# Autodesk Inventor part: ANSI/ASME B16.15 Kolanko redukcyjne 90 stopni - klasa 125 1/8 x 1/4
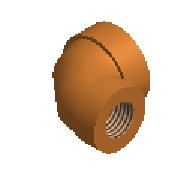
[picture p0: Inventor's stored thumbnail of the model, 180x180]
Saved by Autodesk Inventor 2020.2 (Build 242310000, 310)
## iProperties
Manager: www.cadconsulting.pl
Company: Fabian Stasiak CAD Consulting
Created: 2014-02
Part Number: ANSI/ASME B16.15 Kolanko redukcyjne 90 stopni - klasa 125 1/8 x 1/4
Material: Brąz, odlew
Description: Kolanko redukcyjne 90º odlewane z brązu, gwintowane - klasa 125
Document SubType Name: Modeling
Standard: ANSI/ASME B16.15
Designer: F.Stasiak
Standard Revision: 1985
Standards Organization: ANSI
Language: pl-PL
Size Designation: 1/8 x 1/4
Categories: <MemberInstance><Categories><Category DisplayName="Rury cienko- i grubościenne" InternalName="4347fa0f-2144-441d-94cd-e3e15c92b736" Mnemonic="TUBEANDPIPE"><Cate
Density: 1 g/cm^3
Appearance: Brąz - satynowy
Catalog Web Link: www.expertbooks.pl
NAME: PIPING: ANSI/ASME B16.15 90 Deg Elbow Reducing - Class 125
DATA: <meta><inlinegroups number="0" deflen="0"></inlinegroups><connections number="2"></connections><angles><a>1.5707963267949</a></angles></meta>
IsCustomPart: 0
Author: F.Stasiak
Subject: Zbiór ćwiczeń. Autodesk Inventor 2020. Kurs Professional
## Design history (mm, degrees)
sketch "Sketch1"
  geometry: L1 (0, 0)-(0, 8.128); L2 (0, 8.128)-(0, 9.754); L3 (0, 9.754)-(0, 16.51); L4 (0, 16.51)-(-6.756, 16.51); L5 (-6.756, 16.51)-(-8.89, 16.51); L6 (-8.89, 16.51)-(-15.24, 16.51); L7 (0, 8.128)-(-5.425, 8.128); L8 (-10.287, 0)-(-10.287, 8.128); L9 (-10.287, 8.128)-(-5.425, 8.128); L10 (-10.287, 0)-(-5.679, 0); L11 (-5.679, 0)-(-5.425, 8.128); L12 (-5.679, 0)-(0, 0); L13 (-8.89, 16.51)-(-8.89, 20.68); L14 (-8.89, 20.68)-(-15.24, 20.878); L15 (-15.24, 20.878)-(-15.24, 16.51); L16 (-8.89, 20.68)-(-8.89, 25.019); L17 (-8.89, 25.019)-(-15.24, 25.019); L18 (-15.24, 25.019)-(-15.24, 20.878); A1 r 6.756 centre (-6.756, 9.754) between (0, 9.754) and (-6.756, 16.51)
  constraints: 36 end point, 6 parallel, 5 collinear, 3 perpendicular, 2 point on circle, 2 tangent, 1 centre point, 1 horizontal, 1 vertical, 1 other
  dimensions: "d0" = 8.128 distance of L1.start L1.end (derived); "d1" = 1.6256 distance of L1.end L2.end (derived); "d2" = 16.51 distance of L1.start L3.end (derived); "d3" = 6.35 distance of L5.end L6.end (derived); "d4" = 15.24 distance of L6.end L3.end (derived); "d27" = 20.574 diameter of L8.start L1 (derived); "d28" = 11.35863 diameter of L10.end L1 (derived); "d29" = 1.78991 deg angle of L1 L11; "d30" = 1.78991 deg angle of L6 L14; "d31" = 8.73684 diameter of L14.end L6 (derived); "d32" = 17.018 diameter of L17 L6 (derived)
workplane "Work Plane1"
sketch "Sketch2" dims "d6" = 18.796 (derived)
  geometry: L1 (0, 0)-(9.398, 0); 1 further point
  constraints: 2 end point, 1 coincident, 1 horizontal, 1 horizontal alignment, 2 other
workplane "Work Plane2"
sketch "Sketch3"
  geometry: C1 r 7.62 at (0, 16.51); 1 further point
  constraints: 1 centre point, 1 coincident
  dimensions: "d8" = 15.24 diameter of C1 (derived)
sketch "Sketch4"
  geometry: L1 (-8.89, 24.13)-(-8.89, 8.89) reference; L2 (0, 8.128)-(-9.398, 8.128) reference; L3 (-9.398, 8.128)-(-8.89, 8.89); L4 (-9.144, 8.509)-(0, 16.51); 1 further point
  constraints: 4 end point, 1 midpoint, 1 point on line
  dimensions: "d9" = 8.509 distance of point (-2.74, 14.112) L4.start (derived)
workplane "Work Plane3"
sketch "Sketch5"
  geometry: L1 (-9.144, 8.509)-(0, 16.51) reference
workplane "Work Plane4"
sketch "Sketch6"
  geometry: C1 r 8.509 at (8.509, 0); 1 further point
  constraints: 1 centre point, 1 coincident
  dimensions: "d11" = 17.018 diameter of C1 (derived)
loft "Loft1" sketch "Sketch6" dims "d12" = 0, "d13" = 90 deg, "d14" = 0, "d15" = 90 deg, "d16" = 0, "d17" = 90 deg
sketch "Sketch7"
  geometry: C1 r 5.588 at (0, 16.51); 1 further point
  constraints: 1 centre point, 1 coincident
  dimensions: "d18" = 11.176 diameter of C1 (derived)
sketch "Sketch8"
  geometry: C1 r 6.477 at (8.509, 0); 1 further point
  constraints: 1 centre point, 1 coincident
  dimensions: "d19" = 12.954 diameter of C1 (derived)
sketch "Sketch9"
  geometry: C1 r 7.366 at (0, 0); 1 further point
  constraints: 1 centre point, 1 coincident
  dimensions: "d20" = 14.732 diameter of C1 (derived)
loft "Loft2" sketch "Sketch7", "Sketch8", "Sketch9" dims "d21" = 0, "d22" = 90 deg, "d23" = 0, "d24" = 90 deg, "d25" = 0, "d26" = 90 deg
revolve "Revolve1" stored, may be unused: angle "d183" = 90 deg
revolve "Revolve2" stored, may be unused: angle "d184" = 90 deg
workaxis "Work Axis2"
workpoint "Work Point1"
workpoint "Work Point2"
workaxis "Work Axis3"
workpoint "Work Point3"
workpoint "Work Point4"
body "Solid1"
feature "Gwint1" dims "d185" = 25.4, "d186" = 0
feature "Gwint2" dims "d187" = 25.4, "d188" = 0
other parameters: "MD1" = 8.73684 [user parameter], "B1" = 6.35 [user parameter], "G1" = 2.032 [user parameter], "F1" = 11.176 [user parameter], "MD2" = 11.35863 [user parameter], "B2" = 8.128 [user parameter], "G2" = 2.032 [user parameter], "F2" = 14.732 [user parameter], "X" = 16.51 [user parameter], "Z" = 15.24 [user parameter], "H1" = 17.018 [user parameter], "H2" = 20.574 [user parameter], "E1" = 3.556 [user parameter], "E2" = 4.064 [user parameter], "d5" = 8.128 (derived), "d7" = 8.89 (derived), "d10" = 16.51 (derived), "Size_Designation" = 12.345 [user parameter]
